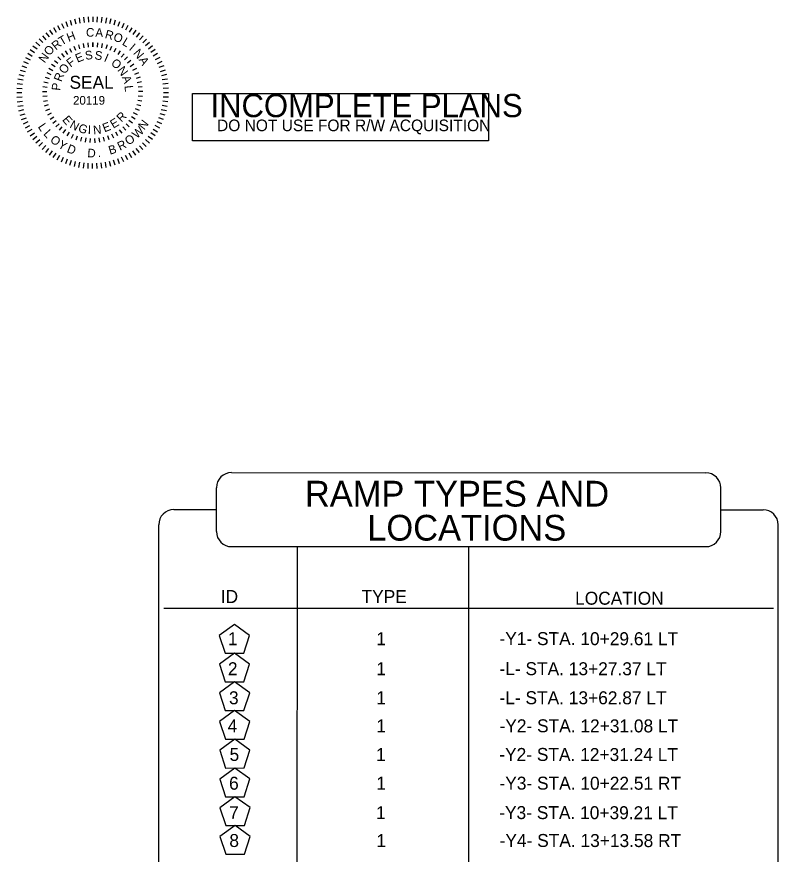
# Model space of a CAD drawing. Extents: x 1726582 to 1728895, y 538986 to 541550.
# Drawn here: x 1728485.1 to 1728895.2, y 539533.7 to 539984.6 of the extents above; entities that cross this region are included whole.
import ezdxf

# ---------------------------------------------------------------- set-up
doc = ezdxf.new("R2010")
doc.units = 0
for name, color, linetype in [('Default', 7, 'Continuous'), ('DEV BORDER CELL', 7, 'Continuous'), ('Gray Area Fill Shapes', 7, 'Continuous'), ('Sheet Sticker Incomplete CELL', 7, 'Continuous'), ('Sheet Title CELL', 7, 'Continuous')]:
    doc.layers.add(name, color=color, linetype=linetype)

msp = doc.modelspace()

# ---------------------------------------------------------------- linework, layer by layer
at = {"layer": 'Default'}
for p, q in [((1728636.06, 539699.31), (1728635.95, 539218.92)), ((1728728.48, 539699.31), (1728728.37, 539218.92)), ((1728564.36, 539666.22), (1728728.48, 539666.18)), ((1728728.48, 539666.18), (1728892.59, 539666.14))]:
    msp.add_line(p, q, dxfattribs=at)
for points in [[(1728602.33, 539657.43), (1728594.22, 539651.5), (1728597.36, 539641.96), (1728607.4, 539641.99), (1728610.48, 539651.55)], [(1728602.38, 539641.97), (1728594.27, 539636.04), (1728597.41, 539626.5), (1728607.46, 539626.53), (1728610.53, 539636.1)], [(1728602.43, 539626.52), (1728594.33, 539620.58), (1728597.46, 539611.04), (1728607.51, 539611.07), (1728610.58, 539620.64)], [(1728602.48, 539611.06), (1728594.38, 539605.13), (1728597.51, 539595.58), (1728607.56, 539595.62), (1728610.63, 539605.18)], [(1728602.54, 539595.6), (1728594.43, 539589.67), (1728597.57, 539580.13), (1728607.61, 539580.16), (1728610.68, 539589.72)], [(1728602.59, 539580.14), (1728594.48, 539574.21), (1728597.62, 539564.67), (1728607.66, 539564.7), (1728610.73, 539574.27)], [(1728602.64, 539564.68), (1728594.53, 539558.75), (1728597.67, 539549.21), (1728607.71, 539549.24), (1728610.79, 539558.81)], [(1728602.69, 539549.23), (1728594.58, 539543.3), (1728597.72, 539533.75), (1728607.77, 539533.79), (1728610.84, 539543.35)]]:
    msp.add_lwpolyline(points, close=True, dxfattribs=at)
at = {"layer": 'DEV BORDER CELL'}
for p, q in [((1728511.56, 539981.93), (1728512.55, 539979.32)), ((1728513.9, 539982.73), (1728514.72, 539980.07)), ((1728516.28, 539983.39), (1728516.94, 539980.69)), ((1728518.69, 539983.91), (1728519.19, 539981.17)), ((1728521.13, 539984.28), (1728521.46, 539981.51)), ((1728523.59, 539984.5), (1728523.76, 539981.72)), ((1728526.06, 539984.57), (1728526.06, 539981.78)), ((1728528.53, 539984.49), (1728528.36, 539981.71)), ((1728530.99, 539984.27), (1728530.65, 539981.5)), ((1728533.43, 539983.9), (1728532.92, 539981.16)), ((1728535.84, 539983.38), (1728535.17, 539980.67)), ((1728538.22, 539982.71), (1728537.39, 539980.05)), ((1728540.55, 539981.9), (1728539.56, 539979.3)), ((1728502.83, 539977.36), (1728504.41, 539975.06)), ((1728504.91, 539978.7), (1728506.35, 539976.31)), ((1728507.06, 539979.91), (1728508.35, 539977.44)), ((1728509.28, 539980.98), (1728510.42, 539978.44)), ((1728542.83, 539980.95), (1728541.69, 539978.41)), ((1728545.05, 539979.87), (1728543.75, 539977.4)), ((1728547.2, 539978.66), (1728545.76, 539976.27)), ((1728549.27, 539977.31), (1728547.69, 539975.02)), ((1728497.15, 539972.62), (1728499.11, 539970.65)), ((1728498.95, 539974.31), (1728500.79, 539972.23)), ((1728500.85, 539975.9), (1728502.56, 539973.7)), ((1728551.26, 539975.85), (1728549.54, 539973.66)), ((1728553.16, 539974.26), (1728551.31, 539972.18)), ((1728554.95, 539972.57), (1728552.98, 539970.6)), ((1728493.87, 539968.93), (1728496.06, 539967.21)), ((1728495.45, 539970.83), (1728497.54, 539968.98)), ((1728515.89, 539968.66), (1728516.76, 539966.5)), ((1728518.34, 539969.52), (1728519, 539967.29)), ((1728520.87, 539970.14), (1728521.31, 539967.86)), ((1728523.45, 539970.51), (1728523.67, 539968.2)), ((1728526.05, 539970.63), (1728526.05, 539968.31)), ((1728526.05, 539968.31), (1728526.05, 539970.63)), ((1728528.65, 539970.51), (1728528.42, 539968.2)), ((1728531.22, 539970.13), (1728530.78, 539967.85)), ((1728533.75, 539969.5), (1728533.08, 539967.28)), ((1728536.21, 539968.64), (1728535.33, 539966.49)), ((1728556.64, 539970.77), (1728554.56, 539968.93)), ((1728558.22, 539968.87), (1728556.03, 539967.16)), ((1728491.06, 539964.88), (1728493.44, 539963.43)), ((1728492.4, 539966.95), (1728494.69, 539965.36)), ((1728509.17, 539964.72), (1728510.63, 539962.9)), ((1728511.28, 539966.24), (1728512.55, 539964.3)), ((1728513.53, 539967.56), (1728514.6, 539965.5)), ((1728538.56, 539967.54), (1728537.49, 539965.48)), ((1728540.81, 539966.22), (1728539.53, 539964.27)), ((1728542.91, 539964.68), (1728541.46, 539962.87)), ((1728559.68, 539966.88), (1728557.39, 539965.3)), ((1728561.02, 539964.81), (1728558.64, 539963.37)), ((1728488.77, 539960.5), (1728491.3, 539959.36)), ((1728489.85, 539962.72), (1728492.31, 539961.43)), ((1728503.86, 539959.02), (1728505.77, 539957.7)), ((1728505.45, 539961.09), (1728507.22, 539959.59)), ((1728507.22, 539962.99), (1728508.85, 539961.33)), ((1728544.86, 539962.96), (1728543.23, 539961.29)), ((1728546.63, 539961.05), (1728544.85, 539959.55)), ((1728548.21, 539958.98), (1728546.3, 539957.66)), ((1728562.24, 539962.66), (1728559.76, 539961.36)), ((1728563.31, 539960.43), (1728560.77, 539959.3)), ((1728487.01, 539955.89), (1728489.67, 539955.06)), ((1728487.81, 539958.22), (1728490.42, 539957.23)), ((1728501.33, 539954.48), (1728503.46, 539953.55)), ((1728502.49, 539956.81), (1728504.52, 539955.68)), ((1728549.58, 539956.77), (1728547.55, 539955.64)), ((1728550.73, 539954.43), (1728548.6, 539953.51)), ((1728564.26, 539958.15), (1728561.65, 539957.17)), ((1728565.06, 539955.82), (1728562.4, 539955)), ((1728485.82, 539951.1), (1728488.56, 539950.6)), ((1728486.34, 539953.51), (1728489.05, 539952.85)), ((1728500.41, 539952.04), (1728502.62, 539951.33)), ((1728551.65, 539951.99), (1728549.44, 539951.28)), ((1728565.72, 539953.44), (1728563.01, 539952.78)), ((1728566.24, 539951.03), (1728563.5, 539950.53)), ((1728485.22, 539946.2), (1728488, 539946.03)), ((1728485.45, 539948.66), (1728488.21, 539948.32)), ((1728499.28, 539946.97), (1728501.58, 539946.69)), ((1728499.72, 539949.53), (1728501.99, 539949.03)), ((1728552.33, 539949.48), (1728550.07, 539948.99)), ((1728552.77, 539946.92), (1728550.47, 539946.64)), ((1728566.6, 539948.58), (1728563.84, 539948.25)), ((1728566.83, 539946.13), (1728564.04, 539945.96)), ((1728485.15, 539943.73), (1728487.93, 539943.73)), ((1728485.22, 539941.26), (1728488, 539941.43)), ((1728499.09, 539944.37), (1728501.41, 539944.31)), ((1728499.15, 539941.77), (1728501.46, 539941.93)), ((1728552.89, 539941.72), (1728550.58, 539941.89)), ((1728552.96, 539944.32), (1728550.64, 539944.27)), ((1728566.82, 539941.19), (1728564.04, 539941.36)), ((1728566.9, 539943.66), (1728564.11, 539943.66)), ((1728485.44, 539938.81), (1728488.21, 539939.14)), ((1728485.81, 539936.36), (1728488.55, 539936.86)), ((1728499.47, 539939.18), (1728501.75, 539939.57)), ((1728500.02, 539936.64), (1728502.26, 539937.25)), ((1728552.01, 539936.59), (1728549.77, 539937.2)), ((1728550.3, 539939.61), (1728552.59, 539939.22)), ((1728566.22, 539936.29), (1728563.48, 539936.79)), ((1728566.59, 539938.73), (1728563.83, 539939.07)), ((1728486.32, 539933.95), (1728489.03, 539934.61)), ((1728486.98, 539931.57), (1728489.65, 539932.39)), ((1728500.82, 539934.16), (1728503, 539934.98)), ((1728501.86, 539931.78), (1728503.94, 539932.81)), ((1728550.16, 539931.73), (1728548.08, 539932.77)), ((1728551.2, 539934.12), (1728549.03, 539934.94)), ((1728565.04, 539931.5), (1728562.37, 539932.33)), ((1728565.7, 539933.88), (1728563, 539934.54)), ((1728487.79, 539929.24), (1728490.4, 539930.22)), ((1728488.74, 539926.96), (1728491.28, 539928.09)), ((1728503.12, 539929.5), (1728505.1, 539930.72)), ((1728504.6, 539927.36), (1728506.45, 539928.76)), ((1728547.41, 539927.32), (1728545.57, 539928.73)), ((1728548.9, 539929.46), (1728546.92, 539930.68)), ((1728563.28, 539926.89), (1728560.74, 539928.03)), ((1728564.23, 539929.17), (1728561.62, 539930.16)), ((1728489.81, 539924.73), (1728492.28, 539926.03)), ((1728491.02, 539922.58), (1728493.41, 539924.02)), ((1728506.28, 539925.37), (1728507.98, 539926.94)), ((1728508.14, 539923.55), (1728509.68, 539925.28)), ((1728510.17, 539921.92), (1728511.53, 539923.79)), ((1728541.84, 539921.89), (1728540.48, 539923.77)), ((1728543.87, 539923.51), (1728542.33, 539925.25)), ((1728545.73, 539925.33), (1728544.04, 539926.91)), ((1728560.98, 539922.51), (1728558.6, 539923.96)), ((1728562.2, 539924.67), (1728559.73, 539925.96)), ((1728492.36, 539920.51), (1728494.65, 539922.09)), ((1728493.82, 539918.52), (1728496.02, 539920.23)), ((1728495.4, 539916.62), (1728497.49, 539918.46)), ((1728512.34, 539920.49), (1728513.52, 539922.49)), ((1728514.65, 539919.28), (1728515.63, 539921.38)), ((1728517.06, 539918.29), (1728517.83, 539920.48)), ((1728520.09, 539919.8), (1728519.53, 539917.54)), ((1728522.11, 539917.04), (1728522.44, 539919.34)), ((1728524.7, 539916.79), (1728524.81, 539919.11)), ((1728527.3, 539916.78), (1728527.19, 539919.1)), ((1728529.89, 539917.03), (1728529.56, 539919.33)), ((1728532.45, 539917.53), (1728531.89, 539919.79)), ((1728534.94, 539918.27), (1728534.17, 539920.47)), ((1728537.35, 539919.26), (1728536.37, 539921.36)), ((1728539.66, 539920.46), (1728538.48, 539922.47)), ((1728556.59, 539916.56), (1728554.51, 539918.41)), ((1728558.18, 539918.46), (1728555.99, 539920.18)), ((1728559.64, 539920.44), (1728557.35, 539922.03)), ((1728497.09, 539914.82), (1728499.06, 539916.79)), ((1728498.89, 539913.13), (1728500.74, 539915.21)), ((1728500.79, 539911.54), (1728502.5, 539913.73)), ((1728553.1, 539913.08), (1728551.25, 539915.16)), ((1728554.9, 539914.77), (1728552.93, 539916.74)), ((1728502.77, 539910.08), (1728504.36, 539912.37)), ((1728504.84, 539908.73), (1728506.29, 539911.12)), ((1728506.99, 539907.52), (1728508.29, 539909.99)), ((1728544.98, 539907.48), (1728543.69, 539909.95)), ((1728547.14, 539908.7), (1728545.7, 539911.08)), ((1728549.21, 539910.03), (1728547.63, 539912.33)), ((1728551.2, 539911.49), (1728549.49, 539913.69)), ((1728509.21, 539906.44), (1728510.36, 539908.98)), ((1728511.49, 539905.49), (1728512.49, 539908.09)), ((1728513.82, 539904.68), (1728514.66, 539907.34)), ((1728516.21, 539904.02), (1728516.87, 539906.72)), ((1728518.62, 539903.49), (1728519.12, 539906.23)), ((1728521.06, 539903.12), (1728521.39, 539905.89)), ((1728523.52, 539902.9), (1728523.69, 539905.68)), ((1728525.98, 539902.82), (1728525.99, 539905.61)), ((1728528.45, 539902.89), (1728528.29, 539905.67)), ((1728530.91, 539903.12), (1728530.58, 539905.88)), ((1728533.35, 539903.48), (1728532.85, 539906.22)), ((1728535.77, 539904), (1728535.11, 539906.7)), ((1728538.15, 539904.66), (1728537.32, 539907.32)), ((1728540.48, 539905.46), (1728539.49, 539908.07)), ((1728542.76, 539906.41), (1728541.62, 539908.95))]:
    msp.add_line(p, q, dxfattribs=at)
at = {"layer": 'Sheet Sticker Incomplete CELL'}
msp.add_lwpolyline([(1728579.76, 539917.81), (1728579.76, 539943.31), (1728739.25, 539943.31), (1728739.25, 539917.81)], close=True, dxfattribs=at)
at = {"layer": 'Sheet Title CELL'}
for p, q in [((1728600.85, 539739.22), (1728856.12, 539739.08)), ((1728592.67, 539707.49), (1728592.67, 539731.04)), ((1728864.3, 539707.49), (1728864.3, 539730.9)), ((1728569.77, 539719.26), (1728592.67, 539719.26)), ((1728864.3, 539719.2), (1728887.01, 539719.2)), ((1728561.55, 539227.1), (1728561.59, 539711.09)), ((1728895.14, 539227.1), (1728895.19, 539711.02)), ((1728600.85, 539699.31), (1728856.12, 539699.31))]:
    msp.add_line(p, q, dxfattribs=at)
for centre, start, end in [((1728600.85, 539731.04), 90, 180), ((1728856.12, 539730.9), 360, 90), ((1728569.77, 539711.09), 90, 180), ((1728887.01, 539711.02), 360, 90), ((1728600.85, 539707.49), 180, 270), ((1728856.12, 539707.49), 270, 360)]:
    msp.add_arc(centre, 8.18, start, end, dxfattribs=at)

# ---------------------------------------------------------------- texts
at = {"layer": 'Default'}
for s, height, p in [('ID', 6.978, (1728595.01, 539668.98)), ('TYPE', 6.978, (1728670.8, 539668.97)), ('LOCATION', 6.978, (1728785.79, 539668.06)), ('1', 6.98, (1728598.85, 539646.27)), ('1', 6.98, (1728678.74, 539646.27)), ('-Y1- STA. 10+29.61 LT', 6.9784, (1728745.07, 539646.32)), ('2', 6.98, (1728598.85, 539630.1)), ('1', 6.98, (1728678.74, 539630.11)), ('-L- STA. 13+27.37 LT', 6.9784, (1728745.07, 539630.15)), ('3', 6.98, (1728599.43, 539614.46)), ('1', 6.98, (1728678.74, 539614.47)), ('-L- STA. 13+62.87 LT', 6.9784, (1728745.07, 539614.51)), ('4', 6.98, (1728598.71, 539599.34)), ('1', 6.98, (1728678.76, 539599.35)), ('-Y2- STA. 12+31.08 LT', 6.9784, (1728745.09, 539599.39)), ('5', 6.98, (1728599.75, 539583.93)), ('1', 6.98, (1728678.63, 539583.93)), ('-Y2- STA. 12+31.24 LT', 6.9784, (1728744.97, 539583.97)), ('-Y3- STA. 10+22.51 RT', 6.9784, (1728745.07, 539568.52)), ('6', 6.98, (1728599.47, 539568.47)), ('1', 6.98, (1728678.74, 539568.48)), ('7', 6.98, (1728599.49, 539552.61)), ('1', 6.98, (1728678.61, 539552.62)), ('-Y3- STA. 10+39.21 LT', 6.9784, (1728744.94, 539552.66)), ('8', 6.98, (1728599.62, 539537.62)), ('1', 6.98, (1728678.82, 539537.62)), ('-Y4- STA. 13+13.58 RT', 6.9784, (1728745.15, 539537.66))]:
    msp.add_text(s, height=height, rotation=359.9462, dxfattribs=at).set_placement(p)
at = {"layer": 'DEV BORDER CELL'}
for s, height, rotation, p in [('C', 4.64, 357.3039, (1728522.34, 539973.94)), ('A', 4.64, 357.3039, (1728527.41, 539973.84)), ('R', 4.64, 345.2946, (1728532.32, 539973.15)), ('T', 4.64, 30.4466, (1728509.36, 539968.95)), ('H', 4.64, 21.0146, (1728513.1, 539970.96)), ('O', 4.64, 342.2378, (1728536.82, 539971.81)), ('L', 4.64, 329.1015, (1728541.54, 539969.74)), ('O', 4.64, 51.6643, (1728502.88, 539963.23)), ('R', 4.64, 38.6075, (1728506.24, 539966.35)), ('I', 4.64, 319.5261, (1728545.28, 539967.04)), ('N', 4.64, 53.6237, (1728500.21, 539959.31)), ('E', 4.64, 22.8914, (1728517.85, 539959.75)), ('S', 4.64, 7.5951, (1728522.21, 539961.34)), ('S', 4.64, 352.2989, (1728526.85, 539961.72)), ('I', 4.64, 337.0026, (1728531.78, 539960.72)), ('N', 4.64, 310.2316, (1728547.6, 539964.85)), ('O', 4.64, 53.4838, (1728511.05, 539953.39)), ('F', 4.64, 38.1876, (1728514.14, 539957.13)), ('O', 4.64, 321.7064, (1728535.52, 539958.91)), ('A', 4.64, 300.4641, (1728550.66, 539961.42)), ('R', 4.64, 68.7801, (1728509.21, 539949.23)), ('N', 4.64, 306.4101, (1728539.09, 539955.79)), ('SEAL', 6.965, 359.947, (1728513.55, 539945.8)), ('A', 4.64, 291.1139, (1728541.63, 539951.99)), ('P', 4.64, 84.0763, (1728508.5, 539944.63)), ('L', 4.64, 275.8176, (1728543.13, 539947.4)), ('20119', 4.64, 359.947, (1728515.44, 539937.26)), ('R', 4.64, 44.5119, (1728541.55, 539927.51)), ('L', 4.64, 303.882, (1728496.33, 539925.35)), ('E', 4.64, 310.0171, (1728509.38, 539928.97)), ('N', 4.64, 330.8721, (1728513.27, 539925.1)), ('E', 4.64, 20.7549, (1728532.36, 539922.3)), ('E', 4.64, 30.7408, (1728537.13, 539924.28)), ('N', 4.64, 52.154, (1728553.77, 539923.31)), ('L', 4.64, 311.9538, (1728499.2, 539921.36)), ('G', 4.64, 339.6384, (1728517.81, 539922.92)), ('I', 4.64, 357.7332, (1728523.34, 539921.43)), ('N', 4.64, 5.3628, (1728526.49, 539921.27)), ('W', 4.64, 43.2714, (1728549.87, 539918.64)), ('O', 4.64, 320.5966, (1728502.72, 539917.7)), ('Y', 4.64, 329.2691, (1728506.94, 539914.47)), ('O', 4.64, 34.3888, (1728545.3, 539915.16)), ('D', 4.64, 338.2416, (1728511.77, 539911.83)), ('B', 4.64, 16.5636, (1728535.33, 539910.29)), ('R', 4.64, 25.5662, (1728540.69, 539912.4)), ('D', 4.64, 356.0369, (1728523.05, 539909)), ('.', 4.64, 3.7793, (1728528.9, 539908.96))]:
    msp.add_text(s, height=height, rotation=rotation, dxfattribs=at).set_placement(p)
at = {"layer": 'Gray Area Fill Shapes'}
for s, height, p in [('RAMP TYPES AND', 13.8661, (1728640.31, 539720.89)), ('LOCATIONS', 13.866, (1728673.88, 539702.56))]:
    msp.add_text(s, height=height, rotation=360, dxfattribs=at).set_placement(p)
at = {"layer": 'Sheet Sticker Incomplete CELL'}
for s, height, p in [('INCOMPLETE PLANS', 12.499, (1728589.47, 539930.51)), ('DO NOT USE FOR R/W ACQUISITION', 6.2495, (1728592.99, 539922.97))]:
    msp.add_text(s, height=height, dxfattribs=at).set_placement(p)

doc.saveas('drawing.dxf')
